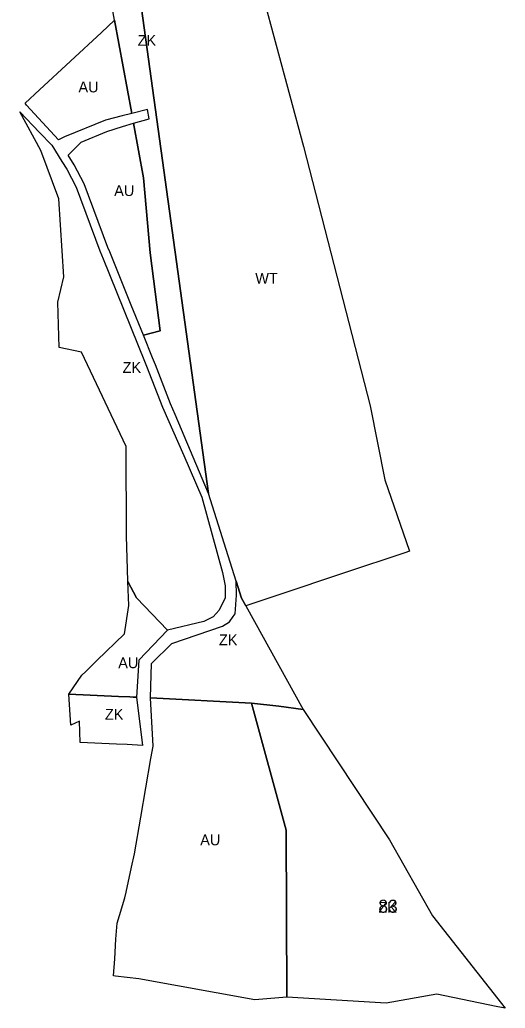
# Model space of a CAD drawing. Extents: x -535894 to -532834, y -1165802 to -1163647.
# Drawn here: x -533058 to -532833.9, y -1165802.2 to -1165345.6 of the extents above; entities that cross this region are included whole.
import ezdxf

# ---------------------------------------------------------------- set-up
doc = ezdxf.new("R2010")
doc.units = 0
for name, color, linetype in [('Vrstva 16', 7, 'Continuous'), ('Vrstva 17', 7, 'Continuous'), ('Vrstva 22', 7, 'Continuous'), ('Vrstva 4', 7, 'Continuous'), ('Vrstva 61', 7, 'Continuous')]:
    doc.layers.add(name, color=color, linetype=linetype)

msp = doc.modelspace()

# ---------------------------------------------------------------- linework, layer by layer
at = {"layer": 'Vrstva 16'}
msp.add_lwpolyline([(-533011.43, -1165270.01), (-532970.84, -1165564.38), (-532986.264, -1165527.956), (-532988.358, -1165523.01), (-532995.402, -1165504.997), (-532996.663, -1165501.772), (-533000.91, -1165491.266), (-532993.193, -1165489.313), (-532997.81, -1165453.19), (-533000.89, -1165418.54), (-533005.487, -1165393.393), (-532998.242, -1165391.325), (-532999.025, -1165387.039), (-533006.318, -1165388.853), (-533014.2, -1165345.74), (-533018.3, -1165323.32)], dxfattribs=at)
for points in [[(-533008.059, -1165604.979), (-533008.26, -1165599.32), (-533008.78, -1165584.18), (-533008.86, -1165542.74), (-533029.56, -1165499.09), (-533039.75, -1165496.98), (-533040.44, -1165475.96), (-533037.58, -1165464.39), (-533039.93, -1165428.22), (-533048.28, -1165406.03), (-533057.97, -1165388.13), (-533048.833, -1165397.671), (-533043.25, -1165403.5), (-533038.485, -1165411.114), (-533036.31, -1165414.59), (-533031.97, -1165422.97), (-533020.99, -1165452.27), (-533019.481, -1165456.002), (-533000.38, -1165503.25), (-532999.491, -1165505.524), (-532992.09, -1165524.45), (-532982.326, -1165546.856), (-532973.97, -1165566.03), (-532964.35, -1165600.88), (-532963.1, -1165607.05), (-532963.13, -1165612.63), (-532966.01, -1165618.23), (-532968.68, -1165621.36), (-532973.06, -1165623.55), (-532989.74, -1165627.54), (-533004.15, -1165612.67)], [(-532958.57, -1165619.96), (-532957.99, -1165611.29), (-532958.061, -1165604.931), (-532955.6, -1165612.74), (-532953.65, -1165616.26), (-532927.21, -1165664.12), (-532938.47, -1165662.64), (-532951, -1165661.3), (-532997.56, -1165658.85), (-532997.2, -1165643), (-532987.76, -1165633.74), (-532964.45, -1165625.74), (-532961.17, -1165623.62), (-532959.419, -1165621.155)], [(-533008.34, -1165680.37), (-533013.39, -1165680.14), (-533030.17, -1165679.38), (-533030.42, -1165669.49), (-533034.47, -1165671.41), (-533035.33, -1165657.07), (-533012.33, -1165658.17), (-533007.17, -1165658.34), (-533005.63, -1165658.42), (-533004.03, -1165658.51), (-533001.3, -1165680.76)]]:
    msp.add_lwpolyline(points, close=True, dxfattribs=at)
at = {"layer": 'Vrstva 17'}
msp.add_lwpolyline([(-532927.21, -1165664.12), (-532887.26, -1165724.36), (-532867.49, -1165759.55), (-532833.91, -1165802.16), (-532838.03, -1165801.32), (-532865.54, -1165795.7), (-532888.93, -1165799.76), (-532934.73, -1165797.08), (-532935.09, -1165719.88), (-532951, -1165661.3), (-532938.47, -1165662.64)], close=True, dxfattribs=at)
at = {"layer": 'Vrstva 22'}
for points in [[(-533037.36, -1165399.59), (-533040.077, -1165401.03), (-533054.81, -1165385.05), (-533055.45, -1165384.16), (-533048.83, -1165378), (-533020.29, -1165351.41), (-533014.2, -1165345.74), (-533006.318, -1165388.853), (-533010.77, -1165389.96), (-533018.33, -1165391.89)], [(-533005.487, -1165393.393), (-533000.89, -1165418.54), (-532997.81, -1165453.19), (-532993.193, -1165489.313), (-533000.91, -1165491.266), (-533006.526, -1165477.375), (-533016.451, -1165452.825), (-533017.262, -1165450.818), (-533028.308, -1165421.343), (-533032.833, -1165412.606), (-533035.604, -1165408.177), (-533029.664, -1165402.123), (-533017.82, -1165397.21), (-533017.717, -1165397.177), (-533010.59, -1165394.85)], [(-533008.059, -1165604.979), (-533004.15, -1165612.67), (-532989.74, -1165627.54), (-533003.06, -1165641.42), (-533004.03, -1165658.51), (-533005.63, -1165658.42), (-533007.17, -1165658.34), (-533012.33, -1165658.17), (-533035.33, -1165657.07), (-533029.26, -1165648.36), (-533027.52, -1165646.64), (-533022.33, -1165641.59), (-533009.63, -1165629.23), (-533007.66, -1165616.19)], [(-532934.73, -1165797.08), (-532949.49, -1165798.31), (-533003, -1165788.63), (-533013.8, -1165787.34), (-533014.65, -1165787.24), (-533014.15, -1165779.42), (-533013.56, -1165770.31), (-533013.08, -1165762.85), (-533011.98, -1165759.36), (-533009.41, -1165751.23), (-533008.83, -1165748.52), (-533006.36, -1165737.02), (-533005.03, -1165730.85), (-533002.12, -1165713.97), (-532997.44, -1165686.82), (-532996.45, -1165681.15), (-532997.56, -1165658.85), (-532951, -1165661.3), (-532935.09, -1165719.88)]]:
    msp.add_lwpolyline(points, close=True, dxfattribs=at)
at = {"layer": 'Vrstva 4'}
msp.add_lwpolyline([(-532880.194, -1165591.758), (-532908.13, -1165601.07), (-532938.91, -1165611.34), (-532953.65, -1165616.26), (-532955.6, -1165612.74), (-532958.061, -1165604.931), (-532970.84, -1165564.38), (-533011.43, -1165270.01), (-533020.388, -1165238.55), (-532971.48, -1165241.706), (-532964.21, -1165259.48), (-532945.97, -1165333.71), (-532926.98, -1165404.07), (-532896.21, -1165523.88), (-532889.53, -1165558.14), (-532878.16, -1165591.08)], close=True, dxfattribs=at)

# ---------------------------------------------------------------- texts
at = {"layer": 'Vrstva 16'}
for rotation, p in [(360, (-533003.563, -1165357.6157)), (0, (-533010.535, -1165508.6693)), (0, (-532966.06, -1165634.5255)), (0, (-533018.6865, -1165668.915))]:
    msp.add_text('ZK', height=5, rotation=rotation, dxfattribs=at).set_placement(p)
at = {"layer": 'Vrstva 17'}
msp.add_text('ZK', height=5, dxfattribs=at).set_placement((-532892.455, -1165758.0401))
at = {"layer": 'Vrstva 22'}
for rotation, p in [(360, (-533030.884, -1165379.1249)), (0, (-533014.3985, -1165426.9977)), (360, (-533012.535, -1165645.1087)), (0, (-532974.69, -1165726.9024))]:
    msp.add_text('AU', height=5, rotation=rotation, dxfattribs=at).set_placement(p)
at = {"layer": 'Vrstva 4'}
msp.add_text('WT', height=5, rotation=0, dxfattribs=at).set_placement((-532949.274, -1165467.5317))
at = {"layer": 'Vrstva 61'}
msp.add_text('83', height=6, rotation=0, dxfattribs=at).set_placement((-532892.455, -1165758.0401))

doc.saveas('drawing.dxf')
